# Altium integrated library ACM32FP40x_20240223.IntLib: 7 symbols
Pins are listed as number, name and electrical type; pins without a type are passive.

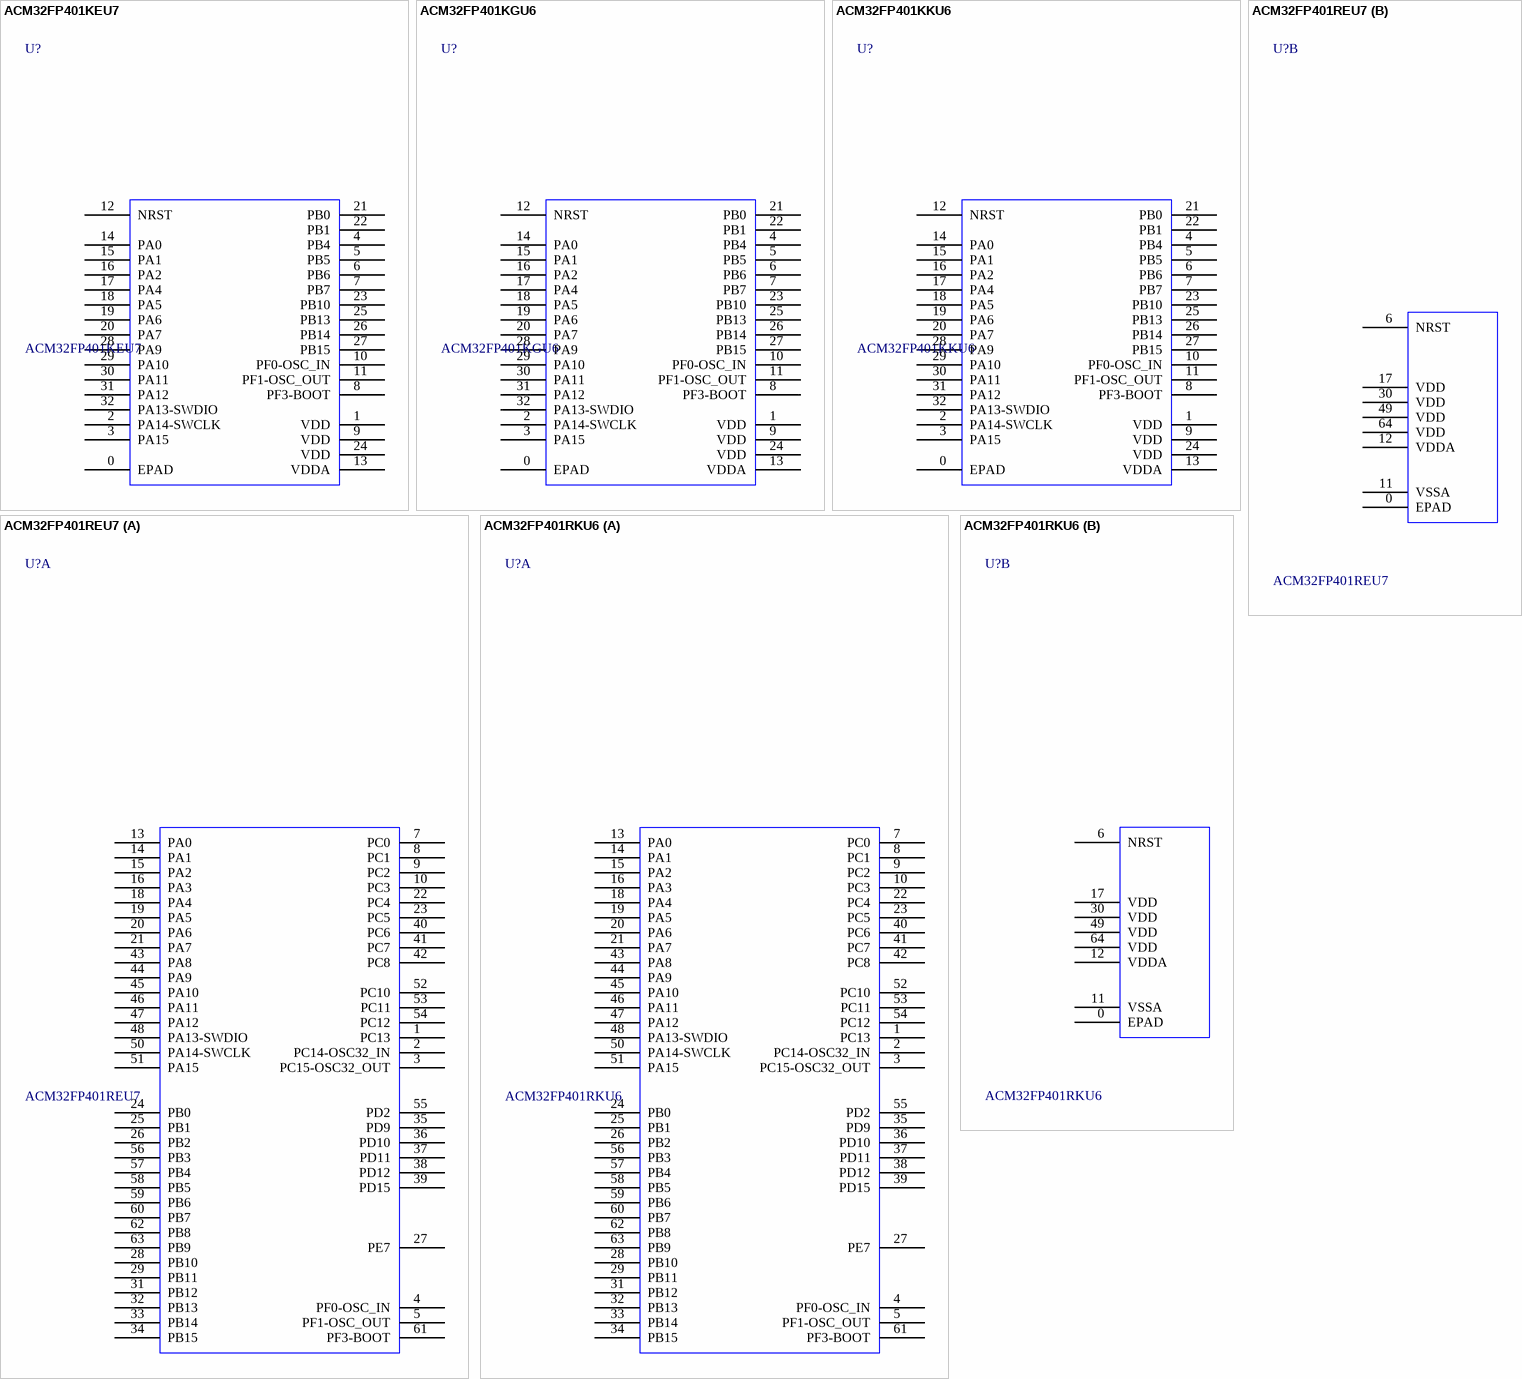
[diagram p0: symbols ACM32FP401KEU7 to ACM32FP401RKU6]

## ACM32FP401KEU7
designator U?
ARM 32-bit Cortex-M33 CPU with FPU
footprint QFN-32_4X4/P.4
pins: 0 EPAD, 1 VDD, 2 PA14-SWCLK, 3 PA15, 4 PB4, 5 PB5, 6 PB6, 7 PB7, 8 PF3-BOOT, 9 VDD, 10 PF0-OSC_IN, 11 PF1-OSC_OUT, 12 NRST, 13 VDDA, 14 PA0, 15 PA1, 16 PA2, 17 PA4, 18 PA5, 19 PA6, 20 PA7, 21 PB0, 22 PB1, 23 PB10, 24 VDD, 25 PB13, 26 PB14, 27 PB15, 28 PA9, 29 PA10, 30 PA11, 31 PA12, 32 PA13-SWDIO

## ACM32FP401KGU6
designator U?
ARM 32-bit Cortex-M33 CPU with FPU
footprint QFN-32_4X4/P.4
pins: 0 EPAD, 1 VDD, 2 PA14-SWCLK, 3 PA15, 4 PB4, 5 PB5, 6 PB6, 7 PB7, 8 PF3-BOOT, 9 VDD, 10 PF0-OSC_IN, 11 PF1-OSC_OUT, 12 NRST, 13 VDDA, 14 PA0, 15 PA1, 16 PA2, 17 PA4, 18 PA5, 19 PA6, 20 PA7, 21 PB0, 22 PB1, 23 PB10, 24 VDD, 25 PB13, 26 PB14, 27 PB15, 28 PA9, 29 PA10, 30 PA11, 31 PA12, 32 PA13-SWDIO

## ACM32FP401KKU6
designator U?
ARM 32-bit Cortex-M33 CPU with FPU
footprint QFN-32_4X4/P.4
pins: 0 EPAD, 1 VDD, 2 PA14-SWCLK, 3 PA15, 4 PB4, 5 PB5, 6 PB6, 7 PB7, 8 PF3-BOOT, 9 VDD, 10 PF0-OSC_IN, 11 PF1-OSC_OUT, 12 NRST, 13 VDDA, 14 PA0, 15 PA1, 16 PA2, 17 PA4, 18 PA5, 19 PA6, 20 PA7, 21 PB0, 22 PB1, 23 PB10, 24 VDD, 25 PB13, 26 PB14, 27 PB15, 28 PA9, 29 PA10, 30 PA11, 31 PA12, 32 PA13-SWDIO

## ACM32FP401REU7
designator U?
ACM32FP401RKU6 Nor_Flash_Internal
footprint QFN-64_8X8/P.4
part A pins: 1 PC13, 2 PC14-OSC32_IN, 3 PC15-OSC32_OUT, 4 PF0-OSC_IN, 5 PF1-OSC_OUT, 7 PC0, 8 PC1, 9 PC2, 10 PC3, 13 PA0, 14 PA1, 15 PA2, 16 PA3, 18 PA4, 19 PA5, 20 PA6, 21 PA7, 22 PC4, 23 PC5, 24 PB0, 25 PB1, 26 PB2, 27 PE7, 28 PB10, 29 PB11, 31 PB12, 32 PB13, 33 PB14, 34 PB15, 35 PD9, 36 PD10, 37 PD11, 38 PD12, 39 PD15, 40 PC6, 41 PC7, 42 PC8, 43 PA8, 44 PA9, 45 PA10, 46 PA11, 47 PA12, 48 PA13-SWDIO, 50 PA14-SWCLK, 51 PA15, 52 PC10, 53 PC11, 54 PC12, 55 PD2, 56 PB3, 57 PB4, 58 PB5, 59 PB6, 60 PB7, 61 PF3-BOOT, 62 PB8, 63 PB9
part B pins: 0 EPAD, 6 NRST, 11 VSSA, 12 VDDA, 17 VDD, 30 VDD, 49 VDD, 64 VDD

## ACM32FP401RKU6
designator U?
ACM32FP401RKU6 Nor_Flash_Internal
footprint QFN-64_8X8/P.4
part A pins: 1 PC13, 2 PC14-OSC32_IN, 3 PC15-OSC32_OUT, 4 PF0-OSC_IN, 5 PF1-OSC_OUT, 7 PC0, 8 PC1, 9 PC2, 10 PC3, 13 PA0, 14 PA1, 15 PA2, 16 PA3, 18 PA4, 19 PA5, 20 PA6, 21 PA7, 22 PC4, 23 PC5, 24 PB0, 25 PB1, 26 PB2, 27 PE7, 28 PB10, 29 PB11, 31 PB12, 32 PB13, 33 PB14, 34 PB15, 35 PD9, 36 PD10, 37 PD11, 38 PD12, 39 PD15, 40 PC6, 41 PC7, 42 PC8, 43 PA8, 44 PA9, 45 PA10, 46 PA11, 47 PA12, 48 PA13-SWDIO, 50 PA14-SWCLK, 51 PA15, 52 PC10, 53 PC11, 54 PC12, 55 PD2, 56 PB3, 57 PB4, 58 PB5, 59 PB6, 60 PB7, 61 PF3-BOOT, 62 PB8, 63 PB9
part B pins: 0 EPAD, 6 NRST, 11 VSSA, 12 VDDA, 17 VDD, 30 VDD, 49 VDD, 64 VDD

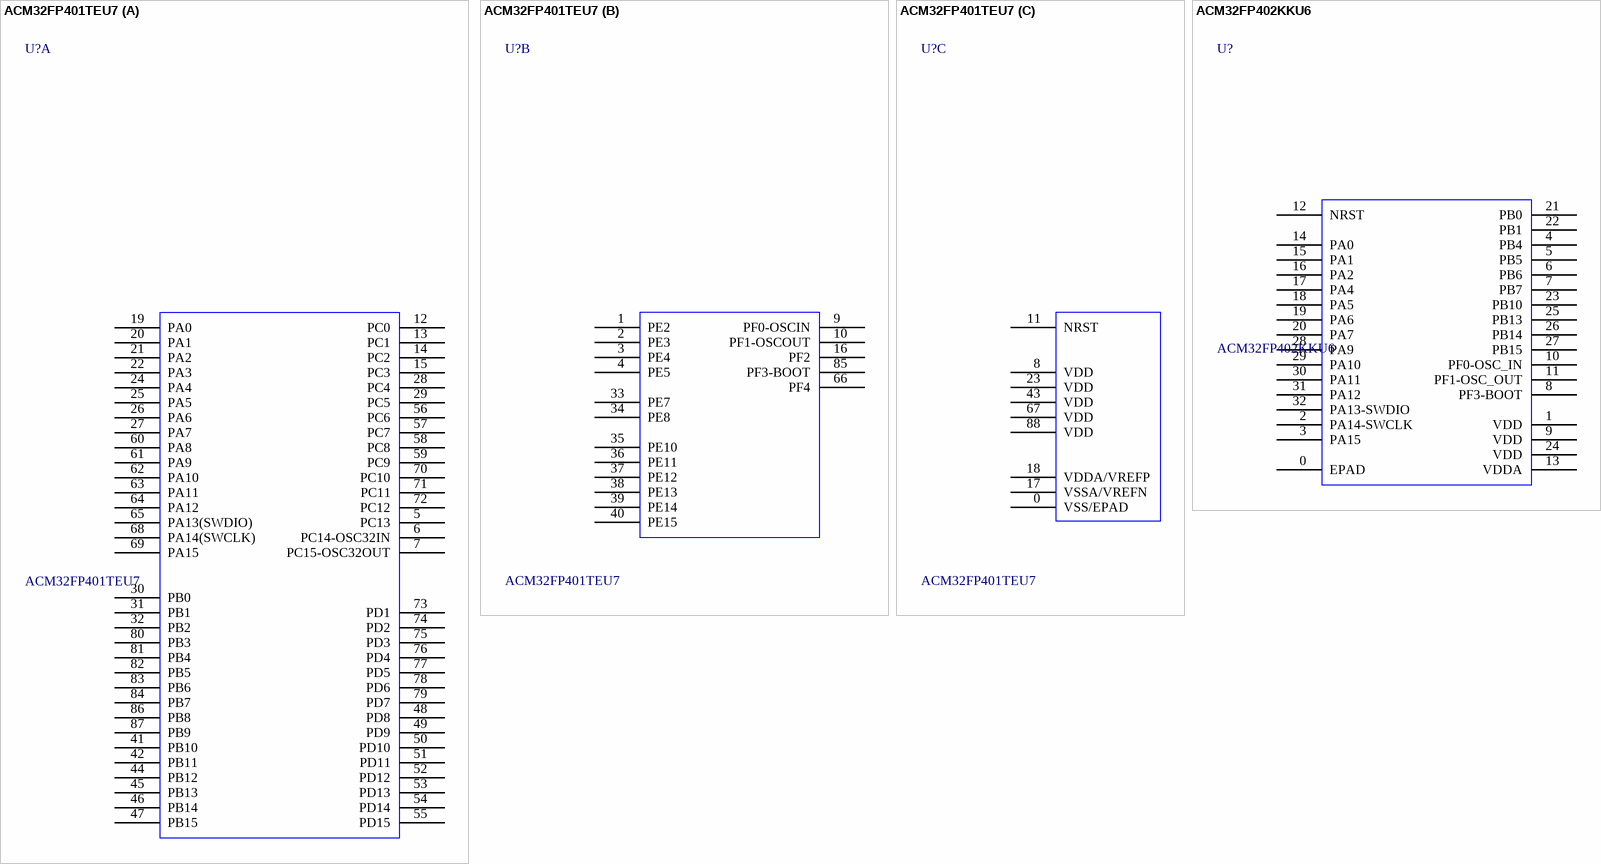
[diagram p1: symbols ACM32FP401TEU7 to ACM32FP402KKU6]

## ACM32FP401TEU7
designator U?
ARM 32-bit Cortex-M33 CPU with FPU & TK
footprint QFN-88_9x9/0.35
part A pins: 5 PC13, 6 PC14-OSC32IN, 7 PC15-OSC32OUT, 12 PC0, 13 PC1, 14 PC2, 15 PC3, 19 PA0, 20 PA1, 21 PA2, 22 PA3, 24 PA4, 25 PA5, 26 PA6, 27 PA7, 28 PC4, 29 PC5, 30 PB0, 31 PB1, 32 PB2, 41 PB10, 42 PB11, 44 PB12, 45 PB13, 46 PB14, 47 PB15, 48 PD8, 49 PD9, 50 PD10, 51 PD11, 52 PD12, 53 PD13, 54 PD14, 55 PD15, 56 PC6, 57 PC7, 58 PC8, 59 PC9, 60 PA8, 61 PA9, 62 PA10, 63 PA11, 64 PA12, 65 PA13(SWDIO), 68 PA14(SWCLK), 69 PA15, 70 PC10, 71 PC11, 72 PC12, 73 PD1, 74 PD2, 75 PD3, 76 PD4, 77 PD5, 78 PD6, 79 PD7, 80 PB3, 81 PB4, 82 PB5, 83 PB6, 84 PB7, 86 PB8, 87 PB9
part B pins: 1 PE2, 2 PE3, 3 PE4, 4 PE5, 9 PF0-OSCIN, 10 PF1-OSCOUT, 16 PF2, 33 PE7, 34 PE8, 35 PE10, 36 PE11, 37 PE12, 38 PE13, 39 PE14, 40 PE15, 66 PF4, 85 PF3-BOOT
part C pins: 0 VSS/EPAD, 8 VDD, 11 NRST, 17 VSSA/VREFN, 18 VDDA/VREFP, 23 VDD, 43 VDD, 67 VDD, 88 VDD

## ACM32FP402KKU6
designator U?
ARM 32-bit Cortex-M33 CPU with FPU
footprint QFN-32_4X4/P.4
pins: 0 EPAD, 1 VDD, 2 PA14-SWCLK, 3 PA15, 4 PB4, 5 PB5, 6 PB6, 7 PB7, 8 PF3-BOOT, 9 VDD, 10 PF0-OSC_IN, 11 PF1-OSC_OUT, 12 NRST, 13 VDDA, 14 PA0, 15 PA1, 16 PA2, 17 PA4, 18 PA5, 19 PA6, 20 PA7, 21 PB0, 22 PB1, 23 PB10, 24 VDD, 25 PB13, 26 PB14, 27 PB15, 28 PA9, 29 PA10, 30 PA11, 31 PA12, 32 PA13-SWDIO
